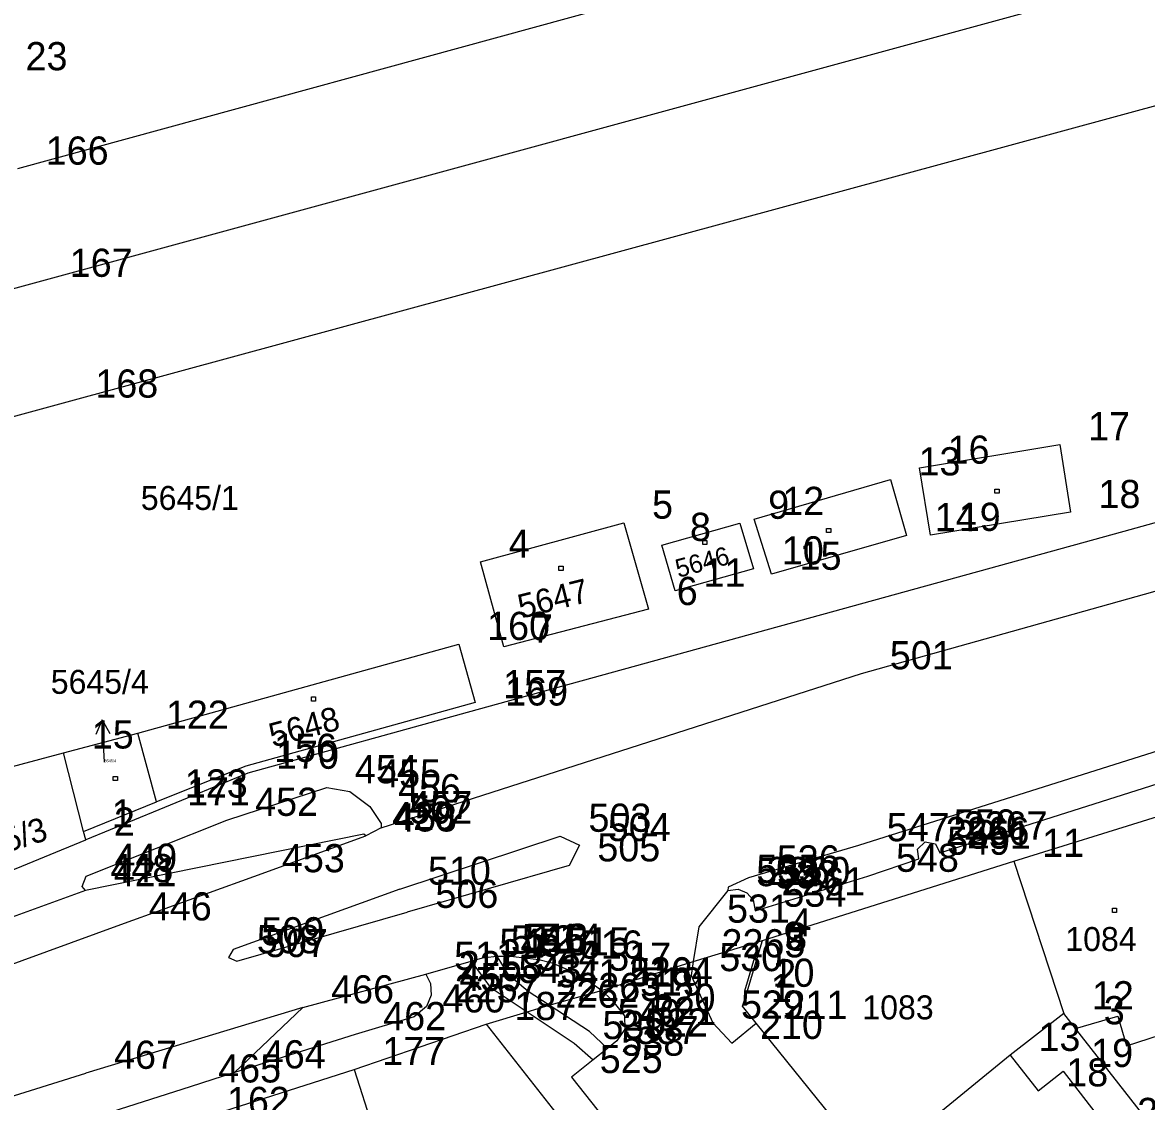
# Model space of a CAD drawing. Extents: x -822293 to -820259, y -1071573 to -1068794.
# Drawn here: x -821657.8 to -821578, y -1070350.9 to -1070274.3 of the extents above; entities that cross this region are included whole.
import ezdxf

# ---------------------------------------------------------------- set-up
doc = ezdxf.new("R2010")
doc.units = 0
for name, color, linetype in [('Vrstva 11', 7, 'Continuous'), ('Vrstva 2', 7, 'Continuous'), ('Vrstva 3', 7, 'Continuous'), ('Vrstva 5', 7, 'Continuous'), ('Vrstva 6', 7, 'Continuous'), ('Vrstva 7', 7, 'Continuous'), ('Vrstva 8', 7, 'Continuous'), ('Vrstva 9', 7, 'Continuous')]:
    doc.layers.add(name, color=color, linetype=linetype)

# ---------------------------------------------------------------- blocks, each defined once
blk = doc.blocks.new('Z61')
at = {"layer": 'Vrstva 2'}
for p, q in [((0, 300), (-50, 200)), ((0, 0), (0, 300)), ((0, 300), (50, 200))]:
    blk.add_line(p, q, dxfattribs=at)
blk = doc.blocks.new('Z402')
at = {"layer": 'Vrstva 2'}
for p, q in [((-10, 10), (20, 10)), ((-10, -20), (-10, 10)), ((20, 10), (20, -20)), ((20, -20), (-10, -20))]:
    blk.add_line(p, q, dxfattribs=at)

msp = doc.modelspace()

# ---------------------------------------------------------------- linework, layer by layer
at = {"layer": 'Vrstva 2'}
for p, q in [((-821654.62, -1070301.25), (-821553.59, -1070273.74)), ((-821521.73, -1070294.49), (-821579.65, -1070310.45)), ((-821720.29, -1070319.13), (-821654.62, -1070301.25)), ((-821625.29, -1070312.61), (-821615.12, -1070309.84)), ((-821615.12, -1070309.84), (-821613.37, -1070315.97)), ((-821612.43, -1070311.42), (-821606.88, -1070309.85)), ((-821606.88, -1070309.85), (-821605.91, -1070313.09)), ((-821579.65, -1070310.45), (-821625.54, -1070323.1)), ((-821611.47, -1070314.66), (-821612.43, -1070311.42)), ((-821623.64, -1070318.64), (-821625.29, -1070312.61)), ((-821605.91, -1070313.09), (-821611.47, -1070314.66)), ((-821613.37, -1070315.97), (-821623.64, -1070318.64)), ((-821649.61, -1070324.75), (-821626.82, -1070318.45)), ((-821626.82, -1070318.45), (-821625.68, -1070322.58)), ((-821625.68, -1070322.58), (-821641.94, -1070327.1)), ((-821625.54, -1070323.1), (-821641.8, -1070327.59)), ((-821654.87, -1070326.15), (-821649.61, -1070324.75)), ((-821648.27, -1070329.63), (-821649.61, -1070324.75)), ((-821666.33, -1070329.2), (-821654.87, -1070326.15)), ((-821653.45, -1070331.75), (-821654.87, -1070326.15)), ((-821641.94, -1070327.1), (-821648.27, -1070329.63)), ((-821641.8, -1070327.59), (-821648.11, -1070330.19)), ((-821653.45, -1070331.75), (-821648.27, -1070329.63)), ((-821648.11, -1070330.19), (-821653.3, -1070332.33)), ((-821587.44, -1070333.84), (-821577.26, -1070330.67)), ((-821663.88, -1070336.66), (-821653.3, -1070332.33)), ((-821653.3, -1070332.33), (-821653.45, -1070331.75)), ((-821605.29, -1070339.48), (-821587.44, -1070333.84)), ((-821587.44, -1070333.84), (-821583.91, -1070344.66)), ((-821610.19, -1070340.97), (-821605.29, -1070339.48)), ((-821605.6, -1070340.5), (-821605.29, -1070339.48)), ((-821616.7, -1070343.02), (-821610.19, -1070340.97)), ((-821606.38, -1070343.11), (-821605.6, -1070340.5)), ((-821620.42, -1070344.07), (-821616.7, -1070343.02)), ((-821606.69, -1070344.14), (-821606.38, -1070343.11)), ((-821621.98, -1070344.54), (-821620.42, -1070344.07)), ((-821605.72, -1070345.34), (-821606.69, -1070344.14)), ((-821624.89, -1070345.42), (-821621.98, -1070344.54)), ((-821583.91, -1070344.66), (-821587.7, -1070347.61)), ((-821583.07, -1070345.72), (-821583.91, -1070344.66)), ((-821634.26, -1070348.62), (-821624.89, -1070345.42)), ((-821624.89, -1070345.42), (-821616.71, -1070355.81)), ((-821597.47, -1070355.58), (-821605.72, -1070345.34)), ((-821576.8, -1070353.71), (-821583.07, -1070345.72)), ((-821587.7, -1070347.61), (-821597.47, -1070355.58)), ((-821645.28, -1070352.16), (-821634.26, -1070348.62)), ((-821634.26, -1070348.62), (-821630.55, -1070360.15))]:
    msp.add_line(p, q, dxfattribs=at)
at = {"layer": 'Vrstva 3'}
for p, q in [((-821558.07, -1070257.3), (-821658.14, -1070284.72)), ((-821555.9, -1070265.25), (-821656.44, -1070292.68)), ((-821656.44, -1070292.68), (-821722.5, -1070310.7)), ((-821594.15, -1070305.94), (-821584.18, -1070304.28)), ((-821584.18, -1070304.28), (-821583.44, -1070309.09)), ((-821593.36, -1070310.71), (-821594.15, -1070305.94)), ((-821605.88, -1070309.58), (-821596.21, -1070306.77)), ((-821596.21, -1070306.77), (-821595.06, -1070310.73)), ((-821583.44, -1070309.09), (-821593.36, -1070310.71)), ((-821604.65, -1070313.47), (-821605.88, -1070309.58)), ((-821595.06, -1070310.73), (-821604.65, -1070313.47)), ((-821598.25, -1070320.53), (-821573.28, -1070313.53)), ((-821632.34, -1070331.48), (-821598.25, -1070320.53)), ((-821565.99, -1070322.47), (-821598.47, -1070332.73)), ((-821592.71, -1070333.26), (-821565.78, -1070324.7)), ((-821643.28, -1070330.93), (-821636.2, -1070328.62)), ((-821636.2, -1070328.62), (-821634.55, -1070328.91)), ((-821634.55, -1070328.91), (-821633.14, -1070329.97)), ((-821633.14, -1070329.97), (-821632.34, -1070331.16)), ((-821653.27, -1070334.9), (-821643.28, -1070330.93)), ((-821632.34, -1070331.48), (-821633.43, -1070332.04)), ((-821632.34, -1070331.16), (-821632.34, -1070331.48)), ((-821633.56, -1070331.94), (-821653.31, -1070335.92)), ((-821641.38, -1070334.93), (-821633.43, -1070332.04)), ((-821633.43, -1070332.04), (-821633.56, -1070331.94)), ((-821631.02, -1070335.82), (-821619.63, -1070332.06)), ((-821619.63, -1070332.06), (-821618.26, -1070332.72)), ((-821618.26, -1070332.72), (-821619, -1070334.16)), ((-821598.47, -1070332.73), (-821606.27, -1070335.02)), ((-821594.29, -1070333), (-821593.73, -1070332.47)), ((-821594.18, -1070333.69), (-821594.29, -1070333)), ((-821593.73, -1070332.47), (-821593.01, -1070332.61)), ((-821593.01, -1070332.61), (-821592.71, -1070333.26)), ((-821597.81, -1070334.9), (-821594.18, -1070333.69)), ((-821619, -1070334.16), (-821630.49, -1070337.46)), ((-821653.55, -1070335.64), (-821653.27, -1070334.9)), ((-821653.31, -1070335.92), (-821653.55, -1070335.64)), ((-821650.82, -1070338.35), (-821641.38, -1070334.93)), ((-821606.27, -1070335.02), (-821607.71, -1070335.68)), ((-821605.8, -1070337.38), (-821597.81, -1070334.9)), ((-821653.31, -1070335.92), (-821667.8, -1070341.18)), ((-821631.02, -1070335.82), (-821642.84, -1070340.12)), ((-821607.73, -1070335.92), (-821609.8, -1070338.51)), ((-821607.71, -1070335.68), (-821607.73, -1070335.92)), ((-821607.73, -1070335.92), (-821607, -1070335.84)), ((-821607, -1070335.84), (-821606.4, -1070336.08)), ((-821606.4, -1070336.08), (-821605.95, -1070336.58)), ((-821605.95, -1070336.58), (-821605.8, -1070337.38)), ((-821642.59, -1070340.95), (-821630.49, -1070337.46)), ((-821671.73, -1070345.95), (-821650.82, -1070338.35)), ((-821609.8, -1070338.51), (-821610.19, -1070340.97)), ((-821642.84, -1070340.12), (-821643.16, -1070340.68)), ((-821643.16, -1070340.68), (-821642.59, -1070340.95)), ((-821629.16, -1070341.86), (-821625.95, -1070340.93)), ((-821625.95, -1070340.93), (-821625.14, -1070340.7)), ((-821625.95, -1070340.93), (-821624.6, -1070342.79)), ((-821625.14, -1070340.7), (-821624.35, -1070340.6)), ((-821624.35, -1070340.6), (-821624.11, -1070340.58)), ((-821624.11, -1070340.58), (-821623.17, -1070340.58)), ((-821623.31, -1070341.91), (-821624.11, -1070340.58)), ((-821623.17, -1070340.58), (-821621.16, -1070340.83)), ((-821621.16, -1070340.83), (-821620.24, -1070341.06)), ((-821620.24, -1070341.06), (-821618.23, -1070341.92)), ((-821610.19, -1070340.97), (-821610.35, -1070341.95)), ((-821605.79, -1070340.44), (-821606.57, -1070343.06)), ((-821605.6, -1070340.5), (-821605.79, -1070340.44)), ((-821637.89, -1070344.24), (-821629.16, -1070341.86)), ((-821629.16, -1070341.86), (-821628.83, -1070342.52)), ((-821621.9, -1070343.1), (-821623.31, -1070341.91)), ((-821618.23, -1070341.92), (-821616.77, -1070342.96)), ((-821610.35, -1070341.95), (-821608.81, -1070345.32)), ((-821628.83, -1070342.52), (-821628.79, -1070343.36)), ((-821624.6, -1070342.79), (-821621.98, -1070344.54)), ((-821628.79, -1070343.36), (-821629.12, -1070344.16)), ((-821620.42, -1070344.07), (-821621.9, -1070343.1)), ((-821616.77, -1070342.96), (-821616.7, -1070343.02)), ((-821616.7, -1070343.02), (-821615.97, -1070343.68)), ((-821606.57, -1070343.06), (-821606.38, -1070343.11)), ((-821637.89, -1070344.24), (-821653.29, -1070348.88)), ((-821642.74, -1070348.85), (-821637.89, -1070344.24)), ((-821629.12, -1070344.16), (-821630, -1070344.88)), ((-821617.56, -1070345.93), (-821620.42, -1070344.07)), ((-821615.97, -1070343.68), (-821615.08, -1070344.83)), ((-821630, -1070344.88), (-821634.19, -1070346.14)), ((-821621.98, -1070344.54), (-821618.64, -1070346.77)), ((-821615.08, -1070344.83), (-821615.04, -1070345.77)), ((-821583.07, -1070345.72), (-821580.07, -1070344.84)), ((-821580.07, -1070344.84), (-821579.45, -1070346.96)), ((-821616.28, -1070347.13), (-821617.56, -1070345.93)), ((-821615.04, -1070345.77), (-821615.61, -1070346.59)), ((-821608.81, -1070345.32), (-821607.46, -1070346.76)), ((-821607.46, -1070346.76), (-821605.72, -1070345.34)), ((-821579.45, -1070346.96), (-821576.11, -1070345.87)), ((-821634.19, -1070346.14), (-821642.74, -1070348.85)), ((-821618.64, -1070346.77), (-821617.3, -1070347.95)), ((-821615.61, -1070346.59), (-821616.28, -1070347.13)), ((-821616.28, -1070347.13), (-821617.3, -1070347.95)), ((-821617.3, -1070347.95), (-821618.83, -1070349.18)), ((-821587.7, -1070347.61), (-821585.73, -1070350.13)), ((-821678.84, -1070356.92), (-821653.29, -1070348.88)), ((-821642.74, -1070348.85), (-821645.9, -1070349.85)), ((-821618.83, -1070349.18), (-821614.92, -1070354.11)), ((-821585.73, -1070350.13), (-821583.96, -1070348.75)), ((-821583.96, -1070348.75), (-821580.7, -1070352.94)), ((-821645.9, -1070349.85), (-821670.92, -1070357.83))]:
    msp.add_line(p, q, dxfattribs=at)
at = {"layer": 'Vrstva 8'}
for p, q in [((-821656.44, -1070292.68), (-821656.44, -1070292.68)), ((-821654.62, -1070301.25), (-821654.62, -1070301.25)), ((-821584.18, -1070304.28), (-821584.18, -1070304.28)), ((-821594.15, -1070305.94), (-821594.15, -1070305.94)), ((-821596.21, -1070306.77), (-821596.21, -1070306.77)), ((-821583.44, -1070309.09), (-821583.44, -1070309.09)), ((-821615.12, -1070309.84), (-821615.12, -1070309.84)), ((-821606.88, -1070309.85), (-821606.88, -1070309.85)), ((-821605.88, -1070309.58), (-821605.88, -1070309.58)), ((-821595.06, -1070310.73), (-821595.06, -1070310.73)), ((-821593.36, -1070310.71), (-821593.36, -1070310.71)), ((-821579.65, -1070310.45), (-821579.65, -1070310.45)), ((-821612.43, -1070311.42), (-821612.43, -1070311.42)), ((-821625.29, -1070312.61), (-821625.29, -1070312.61)), ((-821605.91, -1070313.09), (-821605.91, -1070313.09)), ((-821604.65, -1070313.47), (-821604.65, -1070313.47)), ((-821611.47, -1070314.66), (-821611.47, -1070314.66)), ((-821613.37, -1070315.97), (-821613.37, -1070315.97)), ((-821626.82, -1070318.45), (-821626.82, -1070318.45)), ((-821623.64, -1070318.64), (-821623.64, -1070318.64)), ((-821598.25, -1070320.53), (-821598.25, -1070320.53)), ((-821625.68, -1070322.58), (-821625.68, -1070322.58)), ((-821625.54, -1070323.1), (-821625.54, -1070323.1)), ((-821649.61, -1070324.75), (-821649.61, -1070324.75)), ((-821654.87, -1070326.15), (-821654.87, -1070326.15)), ((-821641.94, -1070327.1), (-821641.94, -1070327.1)), ((-821641.8, -1070327.59), (-821641.8, -1070327.59)), ((-821636.2, -1070328.62), (-821636.2, -1070328.62)), ((-821634.55, -1070328.91), (-821634.55, -1070328.91)), ((-821648.27, -1070329.63), (-821648.27, -1070329.63)), ((-821633.14, -1070329.97), (-821633.14, -1070329.97)), ((-821648.11, -1070330.19), (-821648.11, -1070330.19)), ((-821643.28, -1070330.93), (-821643.28, -1070330.93)), ((-821632.34, -1070331.16), (-821632.34, -1070331.16)), ((-821632.34, -1070331.48), (-821632.34, -1070331.48)), ((-821653.45, -1070331.75), (-821653.45, -1070331.75)), ((-821653.3, -1070332.33), (-821653.3, -1070332.33)), ((-821633.56, -1070331.94), (-821633.56, -1070331.94)), ((-821633.43, -1070332.04), (-821633.43, -1070332.04)), ((-821619.63, -1070332.06), (-821619.63, -1070332.06)), ((-821618.26, -1070332.72), (-821618.26, -1070332.72)), ((-821598.47, -1070332.73), (-821598.47, -1070332.73)), ((-821594.29, -1070333), (-821594.29, -1070333)), ((-821593.73, -1070332.47), (-821593.73, -1070332.47)), ((-821593.01, -1070332.61), (-821593.01, -1070332.61)), ((-821594.18, -1070333.69), (-821594.18, -1070333.69)), ((-821592.71, -1070333.26), (-821592.71, -1070333.26)), ((-821587.44, -1070333.84), (-821587.44, -1070333.84)), ((-821619, -1070334.16), (-821619, -1070334.16)), ((-821653.55, -1070335.64), (-821653.55, -1070335.64)), ((-821653.27, -1070334.9), (-821653.27, -1070334.9)), ((-821641.38, -1070334.93), (-821641.38, -1070334.93)), ((-821606.27, -1070335.02), (-821606.27, -1070335.02)), ((-821597.81, -1070334.9), (-821597.81, -1070334.9)), ((-821653.31, -1070335.92), (-821653.31, -1070335.92)), ((-821631.02, -1070335.82), (-821631.02, -1070335.82)), ((-821607.73, -1070335.92), (-821607.73, -1070335.92)), ((-821607.71, -1070335.68), (-821607.71, -1070335.68)), ((-821607, -1070335.84), (-821607, -1070335.84)), ((-821606.4, -1070336.08), (-821606.4, -1070336.08)), ((-821605.95, -1070336.58), (-821605.95, -1070336.58)), ((-821630.49, -1070337.46), (-821630.49, -1070337.46)), ((-821605.8, -1070337.38), (-821605.8, -1070337.38)), ((-821650.82, -1070338.35), (-821650.82, -1070338.35)), ((-821609.8, -1070338.51), (-821609.8, -1070338.51)), ((-821605.29, -1070339.48), (-821605.29, -1070339.48)), ((-821642.84, -1070340.12), (-821642.84, -1070340.12)), ((-821643.16, -1070340.68), (-821643.16, -1070340.68)), ((-821642.59, -1070340.95), (-821642.59, -1070340.95)), ((-821625.95, -1070340.93), (-821625.95, -1070340.93)), ((-821625.14, -1070340.7), (-821625.14, -1070340.7)), ((-821624.35, -1070340.6), (-821624.35, -1070340.6)), ((-821624.11, -1070340.58), (-821624.11, -1070340.58)), ((-821623.17, -1070340.58), (-821623.17, -1070340.58)), ((-821621.16, -1070340.83), (-821621.16, -1070340.83)), ((-821620.24, -1070341.06), (-821620.24, -1070341.06)), ((-821610.19, -1070340.97), (-821610.19, -1070340.97)), ((-821605.79, -1070340.44), (-821605.79, -1070340.44)), ((-821605.6, -1070340.5), (-821605.6, -1070340.5)), ((-821629.16, -1070341.86), (-821629.16, -1070341.86)), ((-821623.31, -1070341.91), (-821623.31, -1070341.91)), ((-821618.23, -1070341.92), (-821618.23, -1070341.92)), ((-821610.35, -1070341.95), (-821610.35, -1070341.95)), ((-821628.83, -1070342.52), (-821628.83, -1070342.52)), ((-821624.6, -1070342.79), (-821624.6, -1070342.79)), ((-821628.79, -1070343.36), (-821628.79, -1070343.36)), ((-821621.9, -1070343.1), (-821621.9, -1070343.1)), ((-821616.77, -1070342.96), (-821616.77, -1070342.96)), ((-821616.7, -1070343.02), (-821616.7, -1070343.02)), ((-821606.57, -1070343.06), (-821606.57, -1070343.06)), ((-821606.38, -1070343.11), (-821606.38, -1070343.11)), ((-821637.89, -1070344.24), (-821637.89, -1070344.24)), ((-821629.12, -1070344.16), (-821629.12, -1070344.16)), ((-821620.42, -1070344.07), (-821620.42, -1070344.07)), ((-821615.97, -1070343.68), (-821615.97, -1070343.68)), ((-821606.69, -1070344.14), (-821606.69, -1070344.14)), ((-821630, -1070344.88), (-821630, -1070344.88)), ((-821621.98, -1070344.54), (-821621.98, -1070344.54)), ((-821615.08, -1070344.83), (-821615.08, -1070344.83)), ((-821583.91, -1070344.66), (-821583.91, -1070344.66)), ((-821580.07, -1070344.84), (-821580.07, -1070344.84)), ((-821624.89, -1070345.42), (-821624.89, -1070345.42)), ((-821617.56, -1070345.93), (-821617.56, -1070345.93)), ((-821615.04, -1070345.77), (-821615.04, -1070345.77)), ((-821608.81, -1070345.32), (-821608.81, -1070345.32)), ((-821605.72, -1070345.34), (-821605.72, -1070345.34)), ((-821583.07, -1070345.72), (-821583.07, -1070345.72)), ((-821634.19, -1070346.14), (-821634.19, -1070346.14)), ((-821618.64, -1070346.77), (-821618.64, -1070346.77)), ((-821615.61, -1070346.59), (-821615.61, -1070346.59)), ((-821607.46, -1070346.76), (-821607.46, -1070346.76)), ((-821616.28, -1070347.13), (-821616.28, -1070347.13)), ((-821579.45, -1070346.96), (-821579.45, -1070346.96)), ((-821617.3, -1070347.95), (-821617.3, -1070347.95)), ((-821587.7, -1070347.61), (-821587.7, -1070347.61)), ((-821653.29, -1070348.88), (-821653.29, -1070348.88)), ((-821642.74, -1070348.85), (-821642.74, -1070348.85)), ((-821634.26, -1070348.62), (-821634.26, -1070348.62)), ((-821618.83, -1070349.18), (-821618.83, -1070349.18)), ((-821583.96, -1070348.75), (-821583.96, -1070348.75)), ((-821645.9, -1070349.85), (-821645.9, -1070349.85)), ((-821585.73, -1070350.13), (-821585.73, -1070350.13))]:
    msp.add_line(p, q, dxfattribs=at)

# ---------------------------------------------------------------- block references
at = {"layer": 'Vrstva 11', "xscale": 0.01, "yscale": 0.01}
for p in [(-821588.69, -1070307.54), (-821600.64, -1070310.33), (-821609.42, -1070311.18), (-821619.63, -1070313.02), (-821637.19, -1070322.29), (-821651.25, -1070327.93), (-821580.36, -1070337.29)]:
    msp.add_blockref('Z402', p, dxfattribs=at)
at = {"layer": 'Vrstva 7', "xscale": 0.01, "yscale": 0.009999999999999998, "rotation": 3.0000000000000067}
msp.add_blockref('Z61', (-821651.98, -1070326.82), dxfattribs=at)

# ---------------------------------------------------------------- texts
at = {"layer": 'Vrstva 5'}
msp.add_text('5645/1', height=1.7, dxfattribs=at).set_placement((-821649.393, -1070308.92))
at = {"layer": 'Vrstva 6'}
for s, height, rotation, p in [('5646', 1.3, 15, (-821611.26, -1070313.741)), ('5647', 1.7, 14, (-821622.396, -1070316.637)), ('5648', 1.7, 15, (-821640.032, -1070325.778)), ('5645/3', 1.7, 17, (-821662.53, -1070334.34))]:
    msp.add_text(s, height=height, rotation=rotation, dxfattribs=at).set_placement(p)
for s, height, p in [('5645/4', 0.2, (-821651.98, -1070326.82)), ('1084', 1.7, (-821583.796, -1070340.22)), ('1083', 1.7, (-821598.196, -1070345.07))]:
    msp.add_text(s, height=height, dxfattribs=at).set_placement(p)
at = {"layer": 'Vrstva 7'}
msp.add_text('5645/4', height=1.7, dxfattribs=at).set_placement((-821655.78, -1070321.97))
at = {"layer": 'Vrstva 9'}
for s, p in [('23', (-821657.57, -1070277.72)), ('166', (-821656.14, -1070284.42)), ('167', (-821654.44, -1070292.38)), ('168', (-821652.62, -1070300.95)), ('17', (-821582.18, -1070303.98)), ('16', (-821592.15, -1070305.64)), ('13', (-821594.21, -1070306.47)), ('18', (-821581.44, -1070308.79)), ('5', (-821613.12, -1070309.54)), ('9', (-821604.88, -1070309.55)), ('12', (-821603.88, -1070309.28)), ('14', (-821593.06, -1070310.43)), ('19', (-821591.36, -1070310.41)), ('8', (-821610.43, -1070311.12)), ('4', (-821623.29, -1070312.31)), ('10', (-821603.91, -1070312.79)), ('15', (-821602.65, -1070313.17)), ('11', (-821609.47, -1070314.36)), ('6', (-821611.37, -1070315.67)), ('160', (-821624.82, -1070318.15)), ('7', (-821621.64, -1070318.34)), ('501', (-821596.25, -1070320.23)), ('157', (-821623.68, -1070322.28)), ('169', (-821623.54, -1070322.8)), ('122', (-821647.61, -1070324.45)), ('15', (-821652.87, -1070325.85)), ('156', (-821639.94, -1070326.8)), ('170', (-821639.8, -1070327.29)), ('454', (-821634.2, -1070328.32)), ('455', (-821632.55, -1070328.61)), ('123', (-821646.27, -1070329.33)), ('456', (-821631.14, -1070329.67)), ('171', (-821646.11, -1070329.89)), ('452', (-821641.28, -1070330.63)), ('457', (-821630.34, -1070330.86)), ('502', (-821630.34, -1070331.18)), ('1', (-821651.45, -1070331.45)), ('2', (-821651.3, -1070332.03)), ('420', (-821631.56, -1070331.64)), ('458', (-821631.43, -1070331.74)), ('503', (-821617.63, -1070331.76)), ('504', (-821616.26, -1070332.42)), ('547', (-821596.47, -1070332.43)), ('2266', (-821592.29, -1070332.7)), ('550', (-821591.73, -1070332.17)), ('2267', (-821591.01, -1070332.31)), ('549', (-821592.18, -1070333.39)), ('551', (-821590.71, -1070332.96)), ('11', (-821585.44, -1070333.54)), ('505', (-821617, -1070333.86)), ('449', (-821651.27, -1070334.6)), ('453', (-821639.38, -1070334.63)), ('536', (-821604.27, -1070334.72)), ('548', (-821595.81, -1070334.6)), ('448', (-821651.55, -1070335.34)), ('421', (-821651.31, -1070335.62)), ('510', (-821629.02, -1070335.52)), ('532', (-821605.73, -1070335.62)), ('535', (-821605.71, -1070335.38)), ('2260', (-821605, -1070335.54)), ('533', (-821604.4, -1070335.78)), ('2261', (-821603.95, -1070336.28)), ('506', (-821628.49, -1070337.16)), ('534', (-821603.8, -1070337.08)), ('446', (-821648.82, -1070338.05)), ('531', (-821607.8, -1070338.21)), ('4', (-821603.29, -1070339.18)), ('509', (-821640.84, -1070339.82)), ('508', (-821641.16, -1070340.38)), ('507', (-821640.59, -1070340.65)), ('545', (-821623.95, -1070340.63)), ('512', (-821623.14, -1070340.4)), ('546', (-821622.35, -1070340.3)), ('513', (-821622.11, -1070340.28)), ('514', (-821621.17, -1070340.28)), ('515', (-821619.16, -1070340.53)), ('516', (-821618.24, -1070340.76)), ('2265', (-821608.19, -1070340.67)), ('9', (-821603.79, -1070340.14)), ('3', (-821603.6, -1070340.2)), ('511', (-821627.16, -1070341.56)), ('544', (-821621.31, -1070341.61)), ('517', (-821616.23, -1070341.62)), ('530', (-821608.35, -1070341.65)), ('2258', (-821626.83, -1070342.22)), ('459', (-821626.79, -1070343.06)), ('543', (-821622.6, -1070342.49)), ('541', (-821619.9, -1070342.8)), ('2264', (-821614.77, -1070342.66)), ('518', (-821614.7, -1070342.72)), ('10', (-821604.57, -1070342.76)), ('2', (-821604.38, -1070342.81)), ('466', (-821635.89, -1070343.94)), ('2257', (-821627.12, -1070343.86)), ('2263', (-821618.42, -1070343.77)), ('519', (-821613.97, -1070343.38)), ('1', (-821604.69, -1070343.84)), ('460', (-821628, -1070344.58)), ('2262', (-821619.98, -1070344.24)), ('520', (-821613.08, -1070344.53)), ('12', (-821581.91, -1070344.36)), ('187', (-821622.89, -1070345.12)), ('540', (-821615.56, -1070345.63)), ('521', (-821613.04, -1070345.47)), ('529', (-821606.81, -1070345.02)), ('211', (-821603.72, -1070345.04)), ('3', (-821581.07, -1070345.42)), ('462', (-821632.19, -1070345.84)), ('522', (-821613.61, -1070346.29)), ('539', (-821616.64, -1070346.47)), ('537', (-821614.28, -1070346.83)), ('210', (-821605.46, -1070346.46)), ('538', (-821615.3, -1070347.65)), ('13', (-821585.7, -1070347.31)), ('467', (-821651.29, -1070348.58)), ('464', (-821640.74, -1070348.55)), ('177', (-821632.26, -1070348.32)), ('19', (-821581.96, -1070348.45)), ('465', (-821643.9, -1070349.55)), ('525', (-821616.83, -1070348.88)), ('18', (-821583.73, -1070349.83)), ('162', (-821643.28, -1070351.86)), ('20', (-821578.7, -1070352.64))]:
    msp.add_text(s, height=2, dxfattribs=at).set_placement(p)

doc.saveas('drawing.dxf')
